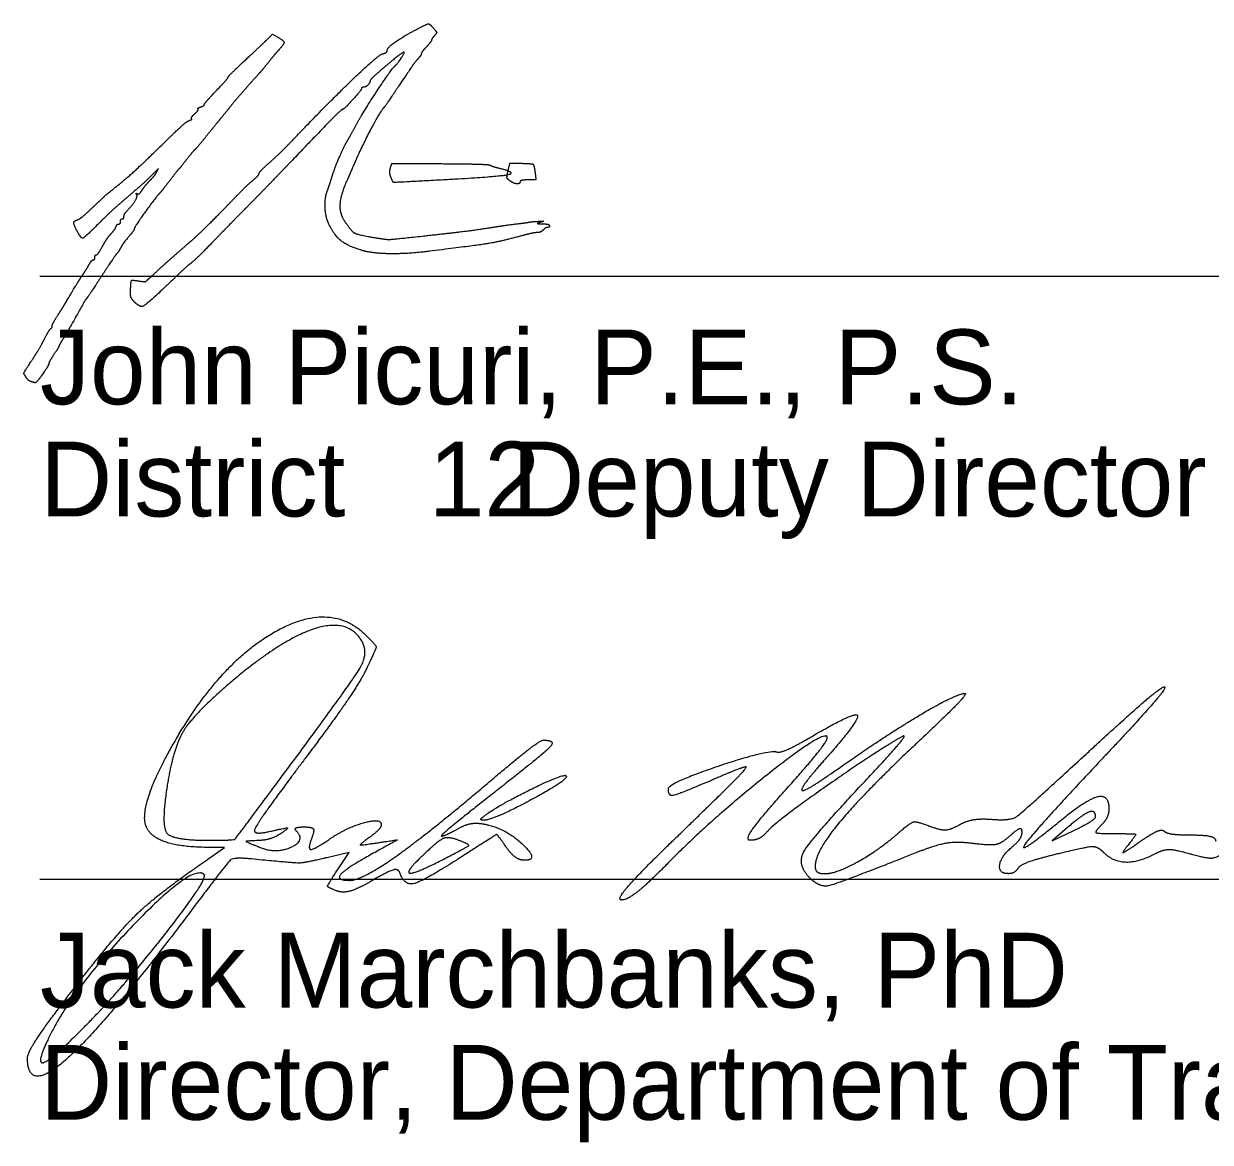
# Model space of a CAD drawing. Extents: x 0 to 34, y -1.2 to 22.
# Drawn here: x 26.784 to 29.006, y 6.123 to 8.217 of the extents above; entities that cross this region are included whole.
import ezdxf

# ---------------------------------------------------------------- set-up
doc = ezdxf.new("R2010")
doc.units = 0
doc.layers.add('SH_Cut_Line', color=7, linetype='Continuous')
doc.layers.add('SH_Data', color=7, linetype='Continuous')

msp = doc.modelspace()

# ---------------------------------------------------------------- linework, layer by layer
at = {"layer": 'SH_Cut_Line'}
for p, q in [((27.4711, 7.9306), (27.4711, 7.9306)), ((27.694, 7.9237), (27.694, 7.9237)), ((26.9896, 7.6982), (26.9896, 7.6982)), ((26.7987, 7.5467), (26.7987, 7.5467)), ((27.2769, 6.8202), (27.2769, 6.8202)), ((27.6423, 6.7303), (27.6423, 6.7303)), ((28.7913, 6.7323), (28.7913, 6.7323)), ((27.5975, 6.6887), (27.5975, 6.6887)), ((28.0141, 6.7013), (28.0141, 6.7013))]:
    msp.add_line(p, q, dxfattribs=at)
for points in [[(27.2395, 8.1872), (27.2503, 8.1978), (27.26, 8.1921)], [(27.5638, 7.9545), (27.4731, 7.955), (27.4705, 7.947)], [(27.7156, 7.9552), (27.6938, 7.9557), (27.6908, 7.942)], [(27.0335, 7.9397), (27.0368, 7.9461), (27.0305, 7.9397)], [(27.7293, 7.9253), (27.7441, 7.9253), (27.7423, 7.9384)], [(28.7395, 6.7127), (28.71, 6.687), (28.7506, 6.7067)], [(27.1293, 6.6532), (27.16, 6.6745), (27.1222, 6.6751)], [(27.3722, 6.6334), (27.3934, 6.6657), (27.3517, 6.6557)]]:
    msp.add_lwpolyline(points, dxfattribs=at)
for points in [[(27.4648, 8.1666), (27.4648, 8.1719), (27.4909, 8.191), (27.517, 8.205)], [(27.517, 8.205), (27.5395, 8.217), (27.5447, 8.2171), (27.5543, 8.2055)], [(27.5543, 8.2055), (27.5578, 8.2013), (27.5576, 8.1994), (27.5533, 8.1946)], [(27.198, 8.1479), (27.2149, 8.1637), (27.2336, 8.1813), (27.2395, 8.1872)], [(27.26, 8.1921), (27.2715, 8.1852), (27.2721, 8.1792), (27.2624, 8.1685)], [(27.548, 8.1865), (27.548, 8.1852), (27.5437, 8.1796), (27.5385, 8.174)], [(27.5533, 8.1946), (27.5504, 8.1914), (27.548, 8.1878), (27.548, 8.1865)], [(27.2624, 8.1685), (27.2584, 8.1641), (27.2494, 8.1534), (27.2424, 8.1447)], [(27.2855, 7.9968), (27.3559, 8.0704), (27.4479, 8.1586), (27.4566, 8.1608)], [(27.4968, 8.1635), (27.4968, 8.1657), (27.4718, 8.1463), (27.4483, 8.1259)], [(27.4566, 8.1608), (27.4611, 8.1619), (27.4648, 8.1645), (27.4648, 8.1666)], [(27.4794, 8.1381), (27.484, 8.1422), (27.4968, 8.1609), (27.4968, 8.1635)], [(27.5289, 8.1611), (27.5288, 8.1597), (27.527, 8.1565), (27.5248, 8.154)], [(27.5385, 8.174), (27.5332, 8.1683), (27.5289, 8.1626), (27.5289, 8.1611)], [(27.1672, 8.1173), (27.1672, 8.1184), (27.1811, 8.1322), (27.198, 8.1479)], [(27.2424, 8.1447), (27.2354, 8.1359), (27.2275, 8.1265), (27.2248, 8.1237)], [(27.4056, 8.0256), (27.4175, 8.0479), (27.4729, 8.1324), (27.4794, 8.1381)], [(27.5248, 8.154), (27.5167, 8.145), (27.5136, 8.1406), (27.4871, 8.1013)], [(27.1448, 8.0917), (27.1572, 8.1046), (27.1672, 8.1161), (27.1672, 8.1173)], [(27.2248, 8.1237), (27.2135, 8.1116), (27.1827, 8.0762), (27.1719, 8.0629)], [(27.4483, 8.1259), (27.4398, 8.1186), (27.4329, 8.1114), (27.4329, 8.1099)], [(27.1224, 8.0658), (27.1224, 8.0672), (27.1325, 8.0788), (27.1448, 8.0917)], [(27.4167, 8.0957), (27.4166, 8.0928), (27.3836, 8.0565), (27.381, 8.0565)], [(27.4203, 8.0981), (27.4184, 8.0981), (27.4168, 8.0971), (27.4167, 8.0957)], [(27.4329, 8.1099), (27.4328, 8.1061), (27.4243, 8.0981), (27.4203, 8.0981)], [(27.4871, 8.1013), (27.4723, 8.0793), (27.4594, 8.0606), (27.4585, 8.0597)], [(27.1158, 8.0613), (27.1195, 8.0624), (27.1224, 8.0645), (27.1224, 8.0658)], [(27.0987, 8.0397), (27.0978, 8.0407), (27.1004, 8.0447), (27.1047, 8.0487)], [(27.1047, 8.0487), (27.109, 8.0526), (27.1117, 8.0566), (27.1108, 8.0575)], [(27.1108, 8.0575), (27.1099, 8.0584), (27.1121, 8.0601), (27.1158, 8.0613)], [(27.1719, 8.0629), (27.1655, 8.055), (27.1556, 8.0428), (27.1498, 8.0357)], [(27.381, 8.0565), (27.3791, 8.0565), (27.3483, 8.0254), (27.2787, 7.9527)], [(27.4585, 8.0597), (27.4517, 8.0533), (27.4121, 7.9773), (27.3993, 7.9461)], [(27.0576, 8.0044), (27.0741, 8.0206), (27.0905, 8.0348), (27.0941, 8.0359)], [(27.0941, 8.0359), (27.0976, 8.037), (27.0997, 8.0387), (27.0987, 8.0397)], [(27.1498, 8.0357), (27.144, 8.0287), (27.1324, 8.0143), (27.1239, 8.0037)], [(27.391, 7.9989), (27.3926, 8.0016), (27.3992, 8.0136), (27.4056, 8.0256)], [(26.965, 7.9182), (26.9824, 7.9324), (27.0163, 7.964), (27.0576, 8.0044)], [(27.1239, 8.0037), (27.1154, 7.9932), (27.1068, 7.9831), (27.1048, 7.9813)], [(27.1048, 7.9813), (27.1027, 7.9796), (27.0955, 7.9709), (27.0886, 7.9621)], [(27.2447, 7.9574), (27.2557, 7.967), (27.2741, 7.9848), (27.2855, 7.9968)], [(27.3609, 7.9285), (27.3658, 7.9449), (27.3842, 7.9879), (27.391, 7.9989)], [(27.0886, 7.9621), (27.0817, 7.9533), (27.0753, 7.9454), (27.0743, 7.9445)], [(27.2248, 7.9366), (27.2248, 7.9384), (27.2338, 7.9477), (27.2447, 7.9574)], [(27.739, 7.9531), (27.7381, 7.954), (27.7275, 7.9549), (27.7156, 7.9552)], [(27.0305, 7.9397), (27.0187, 7.9278), (26.9961, 7.9074), (26.972, 7.8869)], [(27.0208, 7.9237), (27.026, 7.929), (27.0317, 7.9362), (27.0335, 7.9397)], [(27.0743, 7.9445), (27.0733, 7.9437), (27.0657, 7.934), (27.0574, 7.9231)], [(27.2787, 7.9527), (27.2535, 7.9264), (27.2177, 7.8896), (27.1992, 7.8709)], [(27.2132, 7.9237), (27.2196, 7.929), (27.2248, 7.9348), (27.2248, 7.9366)], [(27.3993, 7.9461), (27.3964, 7.9391), (27.3927, 7.9305), (27.391, 7.9269)], [(27.4705, 7.947), (27.4689, 7.9425), (27.4692, 7.9355), (27.4711, 7.9306)], [(27.658, 7.9517), (27.6561, 7.953), (27.6137, 7.9542), (27.5638, 7.9545)], [(27.5704, 7.9253), (27.672, 7.9308), (27.709, 7.9381), (27.6752, 7.9461)], [(27.6752, 7.9461), (27.6677, 7.9479), (27.66, 7.9504), (27.658, 7.9517)], [(27.6908, 7.942), (27.6883, 7.9302), (27.6887, 7.9277), (27.694, 7.9237)], [(27.7423, 7.9384), (27.7414, 7.9456), (27.7398, 7.9522), (27.739, 7.9531)], [(26.9119, 7.8718), (26.9333, 7.892), (26.9389, 7.897), (26.965, 7.9182)], [(27.0058, 7.9054), (27.0089, 7.9102), (27.0157, 7.9185), (27.0208, 7.9237)], [(27.0574, 7.9231), (27.0491, 7.9122), (27.0405, 7.9014), (27.0382, 7.8991)], [(27.1836, 7.8954), (27.1934, 7.9057), (27.2067, 7.9184), (27.2132, 7.9237)], [(27.3526, 7.9036), (27.3542, 7.9076), (27.3579, 7.9189), (27.3609, 7.9285)], [(27.391, 7.9269), (27.3782, 7.8994), (27.3749, 7.8634), (27.384, 7.8492)], [(27.4711, 7.9306), (27.4749, 7.9205), (27.4779, 7.9203), (27.5704, 7.9253)], [(27.694, 7.9237), (27.701, 7.9184), (27.7144, 7.9174), (27.7144, 7.9221)], [(27.7144, 7.9221), (27.7144, 7.9239), (27.7211, 7.9253), (27.7293, 7.9253)], [(26.9762, 7.8651), (26.9878, 7.8771), (26.9979, 7.8935), (26.9958, 7.8969)], [(27.0382, 7.8991), (27.0315, 7.8924), (26.9912, 7.836), (26.9912, 7.8334)], [(26.9958, 7.8969), (26.9944, 7.8992), (26.9948, 7.8999), (26.9968, 7.8987)], [(26.9968, 7.8987), (26.9986, 7.8975), (27.0027, 7.9005), (27.0058, 7.9054)], [(27.0993, 7.8117), (27.1119, 7.8229), (27.1575, 7.8681), (27.1836, 7.8954)], [(27.3544, 7.8449), (27.3491, 7.857), (27.348, 7.8922), (27.3526, 7.9036)], [(26.8851, 7.85), (26.8883, 7.851), (26.9004, 7.8608), (26.9119, 7.8718)], [(26.972, 7.8869), (26.9588, 7.8757), (26.94, 7.8584), (26.9301, 7.8485)], [(27.1992, 7.8709), (27.1808, 7.8521), (27.1523, 7.8231), (27.1361, 7.8063)], [(26.8841, 7.8292), (26.8777, 7.8416), (26.878, 7.8477), (26.8851, 7.85)], [(26.9301, 7.8485), (26.899, 7.8171), (26.8919, 7.8141), (26.8841, 7.8292)], [(26.9623, 7.8421), (26.9642, 7.8421), (26.9656, 7.8443), (26.9656, 7.8469)], [(26.9656, 7.8469), (26.9656, 7.8496), (26.9671, 7.8517), (26.9688, 7.8517)], [(26.9688, 7.8517), (26.9706, 7.8517), (26.972, 7.8538), (26.972, 7.8563)], [(26.972, 7.8563), (26.972, 7.8588), (26.9739, 7.8628), (26.9762, 7.8651)], [(27.4166, 7.7929), (27.3909, 7.8004), (27.3639, 7.823), (27.3544, 7.8449)], [(27.384, 7.8492), (27.3968, 7.8292), (27.41, 7.8218), (27.4427, 7.8164)], [(27.668, 7.8369), (27.6809, 7.839), (27.7109, 7.843), (27.7208, 7.844)], [(27.7208, 7.844), (27.7252, 7.8445), (27.7288, 7.8451), (27.7288, 7.8453)], [(27.7288, 7.8453), (27.7288, 7.8456), (27.736, 7.8464), (27.7448, 7.847)], [(27.7448, 7.847), (27.7566, 7.8479), (27.7587, 7.8475), (27.7528, 7.8455)], [(27.7528, 7.8455), (27.7456, 7.843), (27.746, 7.8427), (27.7568, 7.8425)], [(26.9314, 7.7999), (26.936, 7.8084), (26.9432, 7.819), (26.9474, 7.8236)], [(26.9474, 7.8236), (26.9516, 7.8281), (26.956, 7.8342), (26.9571, 7.837)], [(26.9571, 7.837), (26.9582, 7.8398), (26.9605, 7.8421), (26.9623, 7.8421)], [(26.9912, 7.8334), (26.9912, 7.8313), (26.9879, 7.8267), (26.9725, 7.8083)], [(27.5304, 7.8195), (27.5865, 7.8256), (27.6364, 7.8319), (27.668, 7.8369)], [(27.7454, 7.8261), (27.7416, 7.826), (27.7276, 7.823), (27.7144, 7.8194)], [(27.7572, 7.8309), (27.7545, 7.8283), (27.7492, 7.8261), (27.7454, 7.8261)], [(27.7568, 7.8425), (27.7634, 7.8423), (27.7688, 7.8407), (27.7688, 7.8389)], [(27.7654, 7.8357), (27.7635, 7.8357), (27.7598, 7.8336), (27.7572, 7.8309)], [(27.7688, 7.8389), (27.7688, 7.8372), (27.7673, 7.8357), (27.7654, 7.8357)], [(26.9203, 7.7845), (26.9218, 7.7845), (26.9268, 7.7915), (26.9314, 7.7999)], [(26.9725, 7.8083), (26.971, 7.8065), (26.9679, 7.8014), (26.9656, 7.7971)], [(27.0694, 7.7857), (27.0798, 7.7947), (27.0932, 7.8065), (27.0993, 7.8117)], [(27.1361, 7.8063), (27.1198, 7.7895), (27.1021, 7.7723), (27.0967, 7.7681)], [(27.4427, 7.8164), (27.4634, 7.813), (27.4748, 7.8134), (27.5304, 7.8195)], [(27.7144, 7.8194), (27.6767, 7.8092), (27.6376, 7.8026), (27.5432, 7.791)], [(26.9146, 7.7749), (26.9163, 7.7749), (26.9176, 7.7771), (26.9176, 7.7797)], [(26.9176, 7.7797), (26.9176, 7.7824), (26.9189, 7.7845), (26.9203, 7.7845)], [(26.9594, 7.7877), (26.9582, 7.7869), (26.9454, 7.7681), (26.931, 7.7461)], [(26.9656, 7.7971), (26.9633, 7.7928), (26.9605, 7.7886), (26.9594, 7.7877)], [(27.0313, 7.7514), (27.0418, 7.7612), (27.059, 7.7767), (27.0694, 7.7857)], [(27.5432, 7.791), (27.5025, 7.7859), (27.4368, 7.7869), (27.4166, 7.7929)], [(26.895, 7.7474), (26.8995, 7.7542), (26.9051, 7.7632), (26.9074, 7.7674)], [(26.9074, 7.7674), (26.9097, 7.7715), (26.913, 7.7749), (26.9146, 7.7749)], [(27.0967, 7.7681), (27.0913, 7.764), (27.0766, 7.7506), (27.0639, 7.7384)], [(26.863, 7.6952), (26.8801, 7.7239), (26.8877, 7.7365), (26.895, 7.7474)], [(26.931, 7.7461), (26.9165, 7.7241), (26.9035, 7.7046), (26.902, 7.7027)], [(26.9843, 7.7177), (26.985, 7.7354), (26.9869, 7.7375), (27.0005, 7.7354)], [(27.0639, 7.7384), (27.0163, 7.6926), (27.0017, 7.6848), (26.9896, 7.6982)], [(27.0005, 7.7354), (27.0112, 7.7337), (27.0136, 7.7349), (27.0313, 7.7514)], [(26.9896, 7.6982), (26.9857, 7.7025), (26.984, 7.709), (26.9843, 7.7177)], [(26.848, 7.6713), (26.8538, 7.6802), (26.8605, 7.691), (26.863, 7.6952)], [(26.902, 7.7027), (26.8995, 7.6996), (26.8952, 7.6922), (26.8739, 7.6541)], [(26.8376, 7.6513), (26.8376, 7.6534), (26.8423, 7.6624), (26.848, 7.6713)], [(26.8226, 7.6261), (26.8281, 7.6367), (26.8337, 7.6458), (26.8351, 7.6464)], [(26.8351, 7.6464), (26.8365, 7.647), (26.8376, 7.6492), (26.8376, 7.6513)], [(26.8739, 7.6541), (26.8693, 7.6458), (26.8621, 7.6336), (26.8579, 7.627)], [(26.7982, 7.5849), (26.8062, 7.597), (26.8172, 7.6156), (26.8226, 7.6261)], [(26.8579, 7.627), (26.8538, 7.6204), (26.8504, 7.6144), (26.8504, 7.6136)], [(26.8504, 7.6136), (26.8504, 7.6127), (26.8461, 7.6057), (26.8408, 7.5978)], [(26.7885, 7.5555), (26.784, 7.5624), (26.7846, 7.5641), (26.7982, 7.5849)], [(26.8312, 7.5811), (26.8312, 7.5775), (26.8081, 7.5445), (26.8059, 7.5449)], [(26.8408, 7.5978), (26.8356, 7.59), (26.8312, 7.5825), (26.8312, 7.5811)], [(26.7987, 7.5467), (26.7957, 7.5475), (26.7912, 7.5514), (26.7885, 7.5555)], [(26.8059, 7.5449), (26.8049, 7.5451), (26.8016, 7.5459), (26.7987, 7.5467)], [(27.0657, 6.871), (27.1519, 7.0213), (27.36, 7.1374), (27.4257, 7.0717)], [(27.4167, 7.0625), (27.3908, 7.1045), (27.2647, 7.0634), (27.1693, 6.9818)], [(27.4257, 7.0717), (27.4445, 7.0529), (27.4445, 7.0479), (27.4262, 7.0095)], [(27.2769, 6.8202), (27.3983, 6.9837), (27.4307, 7.0398), (27.4167, 7.0625)], [(27.4262, 7.0095), (27.4152, 6.9865), (27.3635, 6.9109), (27.3112, 6.8415)], [(27.1693, 6.9818), (27.1027, 6.9247), (27.0638, 6.8606), (27.0527, 6.7893)], [(28.3194, 6.8294), (28.3999, 6.886), (28.5312, 6.9633), (28.5469, 6.9633)], [(28.5469, 6.9633), (28.5518, 6.9633), (28.5105, 6.9207), (28.4551, 6.8686)], [(28.7737, 6.8498), (28.8486, 6.9189), (28.9147, 6.9755), (28.9204, 6.9756)], [(28.9204, 6.9756), (28.9261, 6.9757), (28.8741, 6.9156), (28.8048, 6.8419)], [(28.2604, 6.8829), (28.3392, 6.9291), (28.3514, 6.9158), (28.2922, 6.8485)], [(27.1222, 6.6751), (27.0242, 6.6768), (27.0008, 6.7579), (27.0657, 6.871)], [(27.6558, 6.7975), (27.7062, 6.8403), (27.7517, 6.8755), (27.7569, 6.8756)], [(27.7569, 6.8756), (27.7817, 6.8761), (27.7584, 6.8505), (27.6725, 6.7833)], [(28.2885, 6.8827), (28.2789, 6.8923), (28.0691, 6.7254), (27.9913, 6.6461)], [(28.4288, 6.8822), (28.3797, 6.8545), (28.1914, 6.7222), (28.1781, 6.7063)], [(28.1948, 6.8537), (28.2003, 6.8519), (28.2299, 6.865), (28.2604, 6.8829)], [(28.2107, 6.7823), (28.257, 6.834), (28.292, 6.8792), (28.2885, 6.8827)], [(28.4551, 6.8686), (28.3555, 6.7748), (28.2663, 6.6667), (28.2663, 6.6397)], [(28.3636, 6.8033), (28.4097, 6.8526), (28.4391, 6.8881), (28.4288, 6.8822)], [(27.9915, 6.7852), (27.9917, 6.7957), (28.179, 6.8589), (28.1948, 6.8537)], [(28.2922, 6.8485), (28.2642, 6.8167), (28.2413, 6.7871), (28.2413, 6.7826)], [(28.5987, 6.7275), (28.6321, 6.7246), (28.6556, 6.7411), (28.7737, 6.8498)], [(27.3112, 6.8415), (27.259, 6.7722), (27.2163, 6.7115), (27.2163, 6.7068)], [(28.0141, 6.7013), (28.0851, 6.7698), (28.1404, 6.8258), (28.137, 6.8258)], [(28.137, 6.8258), (28.1336, 6.8258), (28.1046, 6.8145), (28.0725, 6.8008)], [(28.2413, 6.7826), (28.2413, 6.7782), (28.2764, 6.7992), (28.3194, 6.8294)], [(28.8048, 6.8419), (28.6753, 6.7044), (28.6432, 6.6571), (28.7253, 6.7249)], [(27.1308, 6.6883), (27.1775, 6.6883), (27.1821, 6.6924), (27.2769, 6.8202)], [(27.6423, 6.7303), (27.6627, 6.7482), (27.7947, 6.814), (27.7999, 6.8088)], [(27.7999, 6.8088), (27.8061, 6.8026), (27.6634, 6.7258), (27.6458, 6.7258)], [(28.0725, 6.8008), (28.0099, 6.7739), (27.9911, 6.7703), (27.9915, 6.7852)], [(28.2565, 6.6177), (28.2313, 6.6429), (28.2602, 6.693), (28.3636, 6.8033)], [(27.0527, 6.7893), (27.0413, 6.716), (27.0627, 6.6883), (27.1308, 6.6883)], [(27.3944, 6.6133), (27.4175, 6.6133), (27.5435, 6.7021), (27.6558, 6.7975)], [(27.6725, 6.7833), (27.5793, 6.7102), (27.5578, 6.6887), (27.6017, 6.7122)], [(28.1448, 6.6883), (28.1346, 6.6883), (28.1634, 6.7296), (28.2107, 6.7823)], [(28.7253, 6.7249), (28.7738, 6.7648), (28.8163, 6.7751), (28.8163, 6.747)], [(28.7913, 6.7323), (28.7913, 6.7458), (28.7672, 6.7367), (28.7395, 6.7127)], [(28.8163, 6.747), (28.8163, 6.7381), (28.8095, 6.724), (28.8013, 6.7158)], [(27.2506, 6.7061), (27.2761, 6.712), (27.2802, 6.7108), (27.2663, 6.7013)], [(27.2953, 6.705), (27.2908, 6.7096), (27.2971, 6.7133), (27.3093, 6.7133)], [(27.3093, 6.7133), (27.3238, 6.7133), (27.329, 6.7068), (27.3242, 6.6945)], [(27.3603, 6.6927), (27.3892, 6.7124), (27.4538, 6.73), (27.4538, 6.718)], [(27.4538, 6.718), (27.4538, 6.7135), (27.444, 6.7027), (27.4321, 6.694)], [(27.6017, 6.7122), (27.6144, 6.719), (27.6383, 6.7211), (27.6549, 6.7169)], [(27.6458, 6.7258), (27.641, 6.7258), (27.6394, 6.7278), (27.6423, 6.7303)], [(27.6549, 6.7169), (27.6909, 6.7077), (27.7493, 6.6508), (27.7226, 6.6508)], [(28.4237, 6.7033), (28.444, 6.7213), (28.4569, 6.724), (28.4806, 6.7149)], [(28.4806, 6.7149), (28.5008, 6.7073), (28.5196, 6.708), (28.5357, 6.717)], [(28.5357, 6.717), (28.549, 6.7245), (28.5774, 6.7292), (28.5987, 6.7275)], [(28.7506, 6.7067), (28.773, 6.7176), (28.7913, 6.7291), (28.7913, 6.7323)], [(28.8013, 6.7158), (28.7896, 6.7041), (28.7955, 6.7008), (28.8278, 6.7008)], [(27.2163, 6.7068), (27.2163, 6.702), (27.2317, 6.7017), (27.2506, 6.7061)], [(27.2663, 6.7013), (27.2559, 6.6944), (27.2363, 6.6882), (27.2225, 6.6877)], [(27.2267, 6.675), (27.2566, 6.663), (27.3128, 6.6876), (27.2953, 6.705)], [(27.3242, 6.6945), (27.3153, 6.6713), (27.3281, 6.6706), (27.3603, 6.6927)], [(27.4321, 6.694), (27.4132, 6.6801), (27.4152, 6.6789), (27.4477, 6.6838)], [(27.4477, 6.6838), (27.4845, 6.6893), (27.4844, 6.6891), (27.4389, 6.664)], [(27.5975, 6.6887), (27.5803, 6.695), (27.5638, 6.6899), (27.5444, 6.6721)], [(27.5694, 6.6524), (27.6157, 6.676), (27.6193, 6.6807), (27.5975, 6.6887)], [(27.6879, 6.6754), (27.671, 6.6995), (27.669, 6.6991), (27.6032, 6.6567)], [(27.9038, 6.5765), (27.8934, 6.5767), (27.9431, 6.6328), (28.0141, 6.7013)], [(28.1781, 6.7063), (28.1699, 6.6964), (28.1549, 6.6883), (28.1448, 6.6883)], [(28.2843, 6.6258), (28.306, 6.6258), (28.3874, 6.671), (28.4237, 6.7033)], [(28.6312, 6.6967), (28.6155, 6.6825), (28.5943, 6.6781), (28.5617, 6.6823)], [(28.6538, 6.7042), (28.6538, 6.7113), (28.6436, 6.708), (28.6312, 6.6967)], [(28.635, 6.6758), (28.6453, 6.6843), (28.6538, 6.6971), (28.6538, 6.7042)], [(28.8278, 6.7008), (28.8653, 6.7008), (28.8677, 6.6987), (28.8522, 6.6794)], [(28.8739, 6.6853), (28.8953, 6.7003), (28.916, 6.7093), (28.92, 6.7054)], [(28.92, 6.7054), (28.9239, 6.7015), (28.9471, 6.6983), (28.9717, 6.6983)], [(28.9717, 6.6983), (28.9962, 6.6983), (29.0163, 6.6931), (29.0163, 6.6868)], [(27.2225, 6.6877), (27.2001, 6.6868), (27.2005, 6.6855), (27.2267, 6.675)], [(27.5444, 6.6721), (27.5001, 6.6317), (27.5114, 6.6228), (27.5694, 6.6524)], [(27.7226, 6.6508), (27.713, 6.6508), (27.6974, 6.6619), (27.6879, 6.6754)], [(28.5617, 6.6823), (28.5324, 6.6861), (28.4926, 6.6796), (28.4561, 6.6652)], [(28.628, 6.6258), (28.6096, 6.6258), (28.6142, 6.6585), (28.635, 6.6758)], [(28.8067, 6.6654), (28.7955, 6.6765), (28.7755, 6.676), (28.7223, 6.6632)], [(28.8522, 6.6794), (28.8401, 6.6644), (28.8466, 6.6661), (28.8739, 6.6853)], [(28.9674, 6.6629), (28.9406, 6.6706), (28.9175, 6.6706), (28.903, 6.6629)], [(29.0565, 6.6743), (29.0192, 6.6558), (29.0006, 6.6534), (28.9674, 6.6629)], [(26.8784, 6.4111), (26.956, 6.5115), (27.0361, 6.5888), (27.1293, 6.6532)], [(27.2105, 6.6534), (27.1771, 6.6567), (27.1654, 6.6462), (27.0887, 6.5445)], [(27.3517, 6.6557), (27.3114, 6.6459), (27.289, 6.6455), (27.2105, 6.6534)], [(27.4389, 6.664), (27.3879, 6.6357), (27.3681, 6.6133), (27.3944, 6.6133)], [(27.6032, 6.6567), (27.5344, 6.6123), (27.4969, 6.6026), (27.4888, 6.627)], [(27.9913, 6.6461), (27.9534, 6.6076), (27.9141, 6.5763), (27.9038, 6.5765)], [(28.4561, 6.6652), (28.3101, 6.6075), (28.275, 6.5992), (28.2565, 6.6177)], [(28.7223, 6.6632), (28.684, 6.654), (28.6497, 6.6418), (28.6462, 6.6361)], [(28.903, 6.6629), (28.8722, 6.6464), (28.8244, 6.6476), (28.8067, 6.6654)], [(27.1222, 6.624), (27.1013, 6.6449), (26.8828, 6.4192), (26.8364, 6.3289)], [(26.9065, 6.3477), (26.9741, 6.4167), (27.1299, 6.6163), (27.1222, 6.624)], [(27.371, 6.5934), (27.3529, 6.6003), (27.353, 6.604), (27.3722, 6.6334)], [(27.4888, 6.627), (27.4859, 6.6355), (27.4667, 6.6303), (27.4376, 6.6132)], [(28.2663, 6.6397), (28.2663, 6.6321), (28.2744, 6.6258), (28.2843, 6.6258)], [(28.6462, 6.6361), (28.6427, 6.6304), (28.6345, 6.6258), (28.628, 6.6258)], [(27.4376, 6.6132), (27.412, 6.5981), (27.382, 6.5891), (27.371, 6.5934)], [(27.0887, 6.5445), (26.9364, 6.3424), (26.7913, 6.2138), (26.7913, 6.2808)], [(26.7913, 6.2808), (26.7913, 6.2904), (26.8305, 6.3491), (26.8784, 6.4111)], [(26.8364, 6.3289), (26.8052, 6.2679), (26.8368, 6.2764), (26.9065, 6.3477)]]:
    msp.add_open_spline(points, degree=2, dxfattribs=at)
at = {"layer": 'SH_Data'}
for p, q in [((26.8147, 7.7446), (30.3147, 7.7446)), ((26.8147, 6.6152), (30.3147, 6.6152))]:
    msp.add_line(p, q, dxfattribs=at)

# ---------------------------------------------------------------- texts
at = {"layer": 'SH_Cut_Line'}
for s, p in [('John Picuri, P.E., P.S.', (26.8147, 7.5046)), ('District      Deputy Director', (26.8147, 7.2946)), ('              12', (26.8147, 7.2946)), ('Jack Marchbanks, PhD', (26.8147, 6.3752)), ('Director, Department of Transportation', (26.8147, 6.1652))]:
    msp.add_text(s, height=0.14, dxfattribs=at).set_placement(p)

doc.saveas('drawing.dxf')
